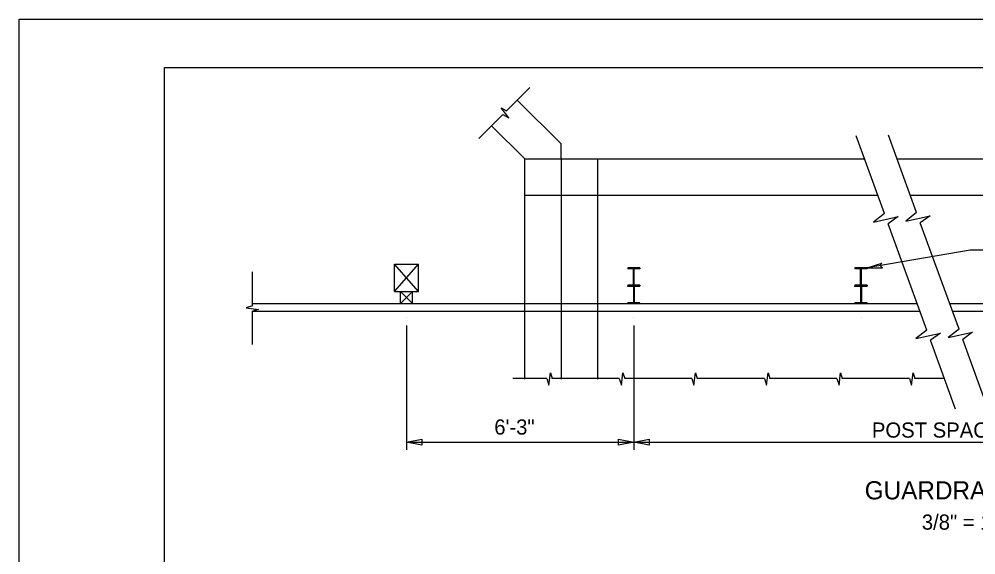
# Model space of a CAD drawing. Extents: x 0 to 90.7, y 0 to 62.8.
# Drawn here: x 0 to 26.31, y 43.93 to 58.67 of the extents above; entities that cross this region are included whole.
import ezdxf

# ---------------------------------------------------------------- set-up
doc = ezdxf.new("R2010")
doc.units = 0
for name, color, linetype in [('BORDER_ANNO_Cutsheet', 7, 'Continuous'), ('BRDG_ANNO_Anno-Sheet', 7, 'Continuous'), ('BRDG_ANNO_General-Notes', 7, 'Continuous'), ('BRDG_BASE_Obj-Line', 7, 'Continuous')]:
    doc.layers.add(name, color=color, linetype=linetype)

msp = doc.modelspace()

# ---------------------------------------------------------------- linework, layer by layer
at = {"layer": 'BORDER_ANNO_Cutsheet'}
msp.add_lwpolyline([(0, 58.667), (90.667, 58.667), (90.667, 0), (0, 0)], close=True, dxfattribs=at)
at = {"layer": 'BRDG_ANNO_Anno-Sheet'}
msp.add_lwpolyline([(4, 57.333), (89.333, 57.333), (89.333, 1.333), (4, 1.333)], close=True, dxfattribs=at)
at = {"layer": 'BRDG_ANNO_General-Notes'}
for p, q in [((26.153, 52.312), (23.32, 51.823)), ((33.592, 52.312), (26.153, 52.312)), ((23.32, 51.823), (23.724, 51.96)), ((23.32, 51.823), (23.747, 51.828)), ((10.653, 50.241), (10.653, 46.824)), ((16.903, 50.241), (16.903, 46.824)), ((10.653, 47.032), (11.073, 47.111)), ((11.073, 47.111), (11.073, 46.953)), ((16.483, 46.953), (16.483, 47.111)), ((16.483, 47.111), (16.903, 47.032)), ((16.903, 47.032), (17.323, 47.111)), ((17.323, 47.111), (17.323, 46.953)), ((10.653, 47.032), (16.903, 47.032)), ((11.073, 46.953), (10.653, 47.032)), ((16.903, 47.032), (16.483, 46.953)), ((16.903, 47.032), (35.653, 47.032)), ((17.323, 46.953), (16.903, 47.032))]:
    msp.add_line(p, q, dxfattribs=at)
msp.add_arc((23.766, 51.9), 0.0741, 125.029, 254.5934, dxfattribs=at)
at = {"layer": 'BRDG_BASE_Obj-Line'}
for p, q in [((14.049, 56.791), (13.405, 56.147)), ((14.903, 55.237), (13.699, 56.441)), ((13.467, 55.955), (13.258, 56.228)), ((13.258, 56.228), (13.405, 56.147)), ((13.299, 56.041), (12.638, 55.38)), ((13.299, 56.041), (13.467, 55.955)), ((13.903, 54.823), (12.992, 55.734)), ((23.797, 53.32), (23.019, 55.456)), ((24.682, 53.345), (23.905, 55.48)), ((14.903, 54.823), (14.903, 55.237)), ((13.903, 48.766), (13.903, 54.823)), ((13.903, 54.823), (23.25, 54.823)), ((14.903, 54.823), (14.903, 48.766)), ((15.903, 54.823), (15.903, 48.766)), ((24.144, 54.823), (38.653, 54.823)), ((13.903, 53.823), (23.614, 53.823)), ((24.508, 53.823), (38.653, 53.823)), ((23.797, 53.32), (23.499, 53.087)), ((23.499, 53.087), (24.17, 53.235)), ((24.17, 53.235), (23.899, 53.039)), ((24.682, 53.345), (24.384, 53.112)), ((24.384, 53.112), (25.056, 53.26)), ((25.056, 53.26), (24.784, 53.063)), ((24.963, 50.115), (23.899, 53.039)), ((25.849, 50.139), (24.784, 53.063)), ((10.32, 51.927), (10.987, 51.927)), ((10.32, 51.177), (10.32, 51.927)), ((10.32, 51.177), (10.987, 51.927)), ((10.987, 51.177), (10.32, 51.927)), ((10.987, 51.177), (10.987, 51.927)), ((6.422, 50.782), (6.422, 51.716)), ((17.07, 51.823), (16.737, 51.823)), ((16.737, 51.823), (16.737, 51.802)), ((16.883, 51.802), (16.737, 51.802)), ((16.893, 51.364), (16.893, 51.792)), ((16.914, 51.364), (16.914, 51.792)), ((17.07, 51.802), (16.924, 51.802)), ((17.07, 51.823), (17.07, 51.802)), ((23.32, 51.823), (22.987, 51.823)), ((22.987, 51.823), (22.987, 51.802)), ((23.133, 51.802), (22.987, 51.802)), ((23.143, 51.364), (23.143, 51.792)), ((23.164, 51.364), (23.164, 51.792)), ((23.32, 51.802), (23.174, 51.802)), ((23.32, 51.823), (23.32, 51.802)), ((16.737, 51.354), (16.737, 51.333)), ((16.883, 51.354), (16.737, 51.354)), ((17.07, 51.333), (16.737, 51.333)), ((17.07, 51.333), (16.737, 51.333)), ((16.737, 51.312), (16.737, 51.333)), ((16.883, 51.312), (16.737, 51.312)), ((17.07, 51.354), (16.924, 51.354)), ((17.07, 51.312), (16.924, 51.312)), ((17.07, 51.354), (17.07, 51.333)), ((17.07, 51.312), (17.07, 51.333)), ((22.987, 51.354), (22.987, 51.333)), ((23.133, 51.354), (22.987, 51.354)), ((23.32, 51.333), (22.987, 51.333)), ((23.32, 51.333), (22.987, 51.333)), ((22.987, 51.312), (22.987, 51.333)), ((23.133, 51.312), (22.987, 51.312)), ((23.32, 51.354), (23.174, 51.354)), ((23.32, 51.312), (23.174, 51.312)), ((23.32, 51.354), (23.32, 51.333)), ((23.32, 51.312), (23.32, 51.333)), ((10.32, 51.177), (10.987, 51.177)), ((10.487, 50.843), (10.487, 51.177)), ((10.487, 51.177), (10.82, 50.843)), ((10.82, 51.177), (10.487, 50.843)), ((10.82, 50.843), (10.82, 51.177)), ((16.893, 51.302), (16.893, 50.875)), ((16.914, 51.302), (16.914, 50.875)), ((23.143, 51.302), (23.143, 50.875)), ((23.164, 51.302), (23.164, 50.875)), ((6.422, 50.782), (6.242, 50.723)), ((6.426, 50.843), (24.698, 50.843)), ((16.737, 50.843), (16.737, 50.864)), ((16.883, 50.864), (16.737, 50.864)), ((17.07, 50.843), (16.737, 50.843)), ((17.07, 50.864), (16.924, 50.864)), ((17.07, 50.843), (17.07, 50.864)), ((22.987, 50.843), (22.987, 50.864)), ((23.133, 50.864), (22.987, 50.864)), ((23.32, 50.843), (22.987, 50.843)), ((23.32, 50.864), (23.174, 50.864)), ((23.32, 50.843), (23.32, 50.864)), ((25.592, 50.843), (44.656, 50.843)), ((6.242, 50.723), (6.583, 50.678)), ((6.583, 50.678), (6.422, 50.632)), ((6.422, 49.721), (6.422, 50.632)), ((6.426, 50.635), (24.774, 50.635)), ((25.668, 50.635), (44.656, 50.635)), ((10.653, 50.449), (10.653, 50.449)), ((16.903, 50.449), (16.903, 50.449)), ((23.153, 50.449), (23.153, 50.449)), ((24.963, 50.115), (24.665, 49.882)), ((24.665, 49.882), (25.337, 50.03)), ((25.337, 50.03), (25.066, 49.834)), ((25.849, 50.139), (25.551, 49.907)), ((25.551, 49.907), (26.222, 50.055)), ((26.222, 50.055), (25.951, 49.858)), ((25.755, 47.938), (25.066, 49.834)), ((26.641, 47.963), (25.951, 49.858)), ((14.567, 48.602), (14.612, 48.943)), ((14.612, 48.943), (14.658, 48.782)), ((16.562, 48.602), (16.607, 48.943)), ((16.607, 48.943), (16.653, 48.782)), ((18.557, 48.602), (18.603, 48.943)), ((18.603, 48.943), (18.649, 48.782)), ((20.553, 48.602), (20.598, 48.943)), ((20.598, 48.943), (20.644, 48.782)), ((22.548, 48.602), (22.593, 48.943)), ((22.593, 48.943), (22.639, 48.782)), ((24.543, 48.602), (24.588, 48.943)), ((24.588, 48.943), (24.634, 48.782)), ((14.509, 48.782), (13.574, 48.782)), ((14.509, 48.782), (14.567, 48.602)), ((15.569, 48.782), (14.658, 48.782)), ((16.504, 48.782), (15.569, 48.782)), ((16.504, 48.782), (16.562, 48.602)), ((17.565, 48.782), (16.653, 48.782)), ((18.499, 48.782), (17.565, 48.782)), ((18.499, 48.782), (18.557, 48.602)), ((19.56, 48.782), (18.649, 48.782)), ((20.494, 48.782), (19.56, 48.782)), ((20.494, 48.782), (20.553, 48.602)), ((21.555, 48.782), (20.644, 48.782)), ((22.49, 48.782), (21.555, 48.782)), ((22.49, 48.782), (22.548, 48.602)), ((23.55, 48.782), (22.639, 48.782)), ((24.485, 48.782), (23.55, 48.782)), ((24.485, 48.782), (24.543, 48.602)), ((25.448, 48.782), (24.634, 48.782))]:
    msp.add_line(p, q, dxfattribs=at)
for centre, start, end in [((16.883, 51.792), 0, 90), ((16.924, 51.792), 90, 180), ((23.133, 51.792), 0, 90), ((23.174, 51.792), 90, 180), ((16.883, 51.364), 270, 0), ((16.883, 51.302), 0, 90), ((16.924, 51.364), 180, 270), ((16.924, 51.302), 90, 180), ((23.133, 51.364), 270, 0), ((23.133, 51.302), 0, 90), ((23.174, 51.364), 180, 270), ((23.174, 51.302), 90, 180), ((16.883, 50.875), 270, 360), ((16.924, 50.875), 180, 270), ((23.133, 50.875), 270, 360), ((23.174, 50.875), 180, 270)]:
    msp.add_arc(centre, 0.0104, start, end, dxfattribs=at)

# ---------------------------------------------------------------- texts
at = {"layer": 'BRDG_ANNO_General-Notes'}
for s, height, p in [('6\'-3"', 0.4167, (13.067, 47.241)), ('POST SPACING 6\'-3"', 0.41667, (23.452, 47.157)), ('GUARDRAIL PLAN', 0.5, (23.254, 45.459)), ('3/8" = 1\'-0"', 0.41667, (24.825, 44.626))]:
    msp.add_text(s, height=height, dxfattribs=at).set_placement(p)

doc.saveas('drawing.dxf')
